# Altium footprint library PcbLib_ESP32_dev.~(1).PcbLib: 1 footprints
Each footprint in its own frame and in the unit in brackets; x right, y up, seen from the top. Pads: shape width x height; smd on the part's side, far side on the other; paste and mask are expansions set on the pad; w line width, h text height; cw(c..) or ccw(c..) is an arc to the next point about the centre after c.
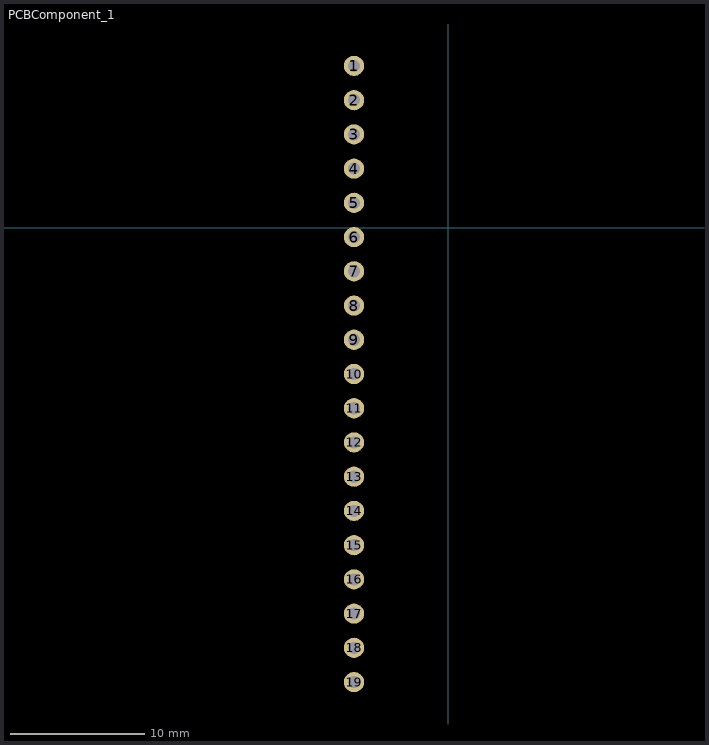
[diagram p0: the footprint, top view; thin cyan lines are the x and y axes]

## PCBComponent_1 [mm]
pads (19):
  round 1.5 hole 0.9: 1(-6.985,12) 2(-6.985,9.46) 3(-6.985,6.92) 4(-6.985,4.38) 5(-6.985,1.84) 6(-6.985,-0.7) 7(-6.985,-3.24) 8(-6.985,-5.78) 9(-6.985,-8.32) 10(-6.985,-10.86) 11(-6.985,-13.4) 12(-6.985,-15.94) 13(-6.985,-18.48) 14(-6.985,-21.02) 15(-6.985,-23.56) 16(-6.985,-26.1) 17(-6.985,-28.64) 18(-6.985,-31.18) 19(-6.985,-33.72)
